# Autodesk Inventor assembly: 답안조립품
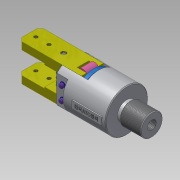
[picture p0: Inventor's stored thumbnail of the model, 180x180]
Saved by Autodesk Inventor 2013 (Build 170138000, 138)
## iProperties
Created: 2019-02
Part Number: 답안조립품
Document SubType Name: Assembly
Designer: Administrator
Author: Administrator
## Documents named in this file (11)
- C:\Users\Administrator\Desktop\490207V1012\답안조립품.iam
- C:\Users\Administrator\Desktop\490207V1012\본체.ipt
- C:\Users\Administrator\Desktop\490207V1012\E-링.ipt
- C:\Users\Administrator\Desktop\490207V1012\O-링.ipt
- C:\Users\Administrator\Desktop\490207V1012\가이드핀.ipt
- C:\Users\Administrator\Desktop\490207V1012\부시.ipt
- C:\Users\Administrator\Desktop\490207V1012\스프링.ipt
- C:\Users\Administrator\Desktop\490207V1012\평행핀 6x28.ipt
- C:\Users\Administrator\Desktop\490207V1012\피스톤.ipt
- C:\Users\Administrator\Desktop\490207V1012\핀.ipt
- C:\Users\Administrator\Desktop\490207V1012\핑거.ipt
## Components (13 placed, 6 different names)
1. E-링:1
2. O-링:1
3. 가이드핀:1
4. 피스톤:1 — 각도:1
5. 핀:1
6. 핑거:1 — 각도:1
7. O-링:2
8. 핑거:2 — 플러쉬:1
9. 핀:2
10. E-링:2
11. E-링:3
12. E-링:4
13. 가이드핀:2
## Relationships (2: Flush 1, Angle 1)
- 플러쉬:1 [Flush]: 핑거:2
- 각도:1 [Angle]: 피스톤:1 ↔ 핑거:1
